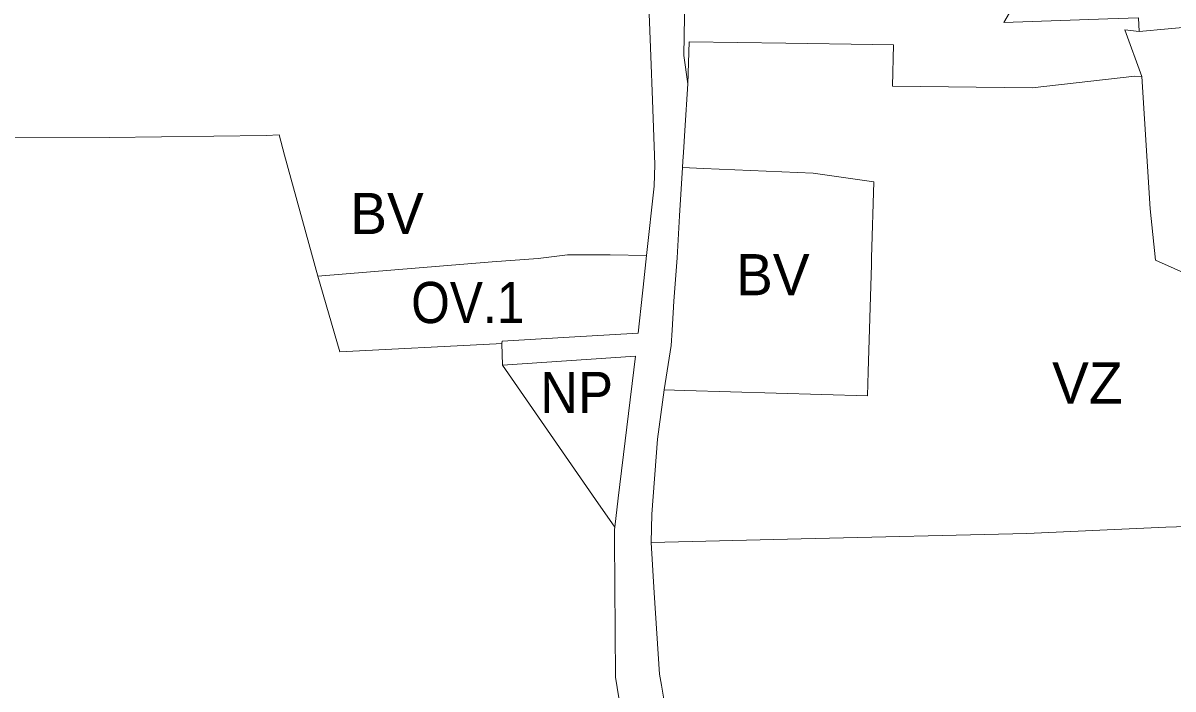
# Model space of a CAD drawing. Extents: x -650451 to -642268, y -1075216 to -1066610.
# Drawn here: x -643994.3 to -643659.8, y -1070322.5 to -1070128.6 of the extents above; entities that cross this region are included whole.
import ezdxf

# ---------------------------------------------------------------- set-up
doc = ezdxf.new("R2010")
doc.units = 0
doc.header["$LTSCALE"] = 4.8
for name, color, linetype, lineweight in [('11', 7, 'Continuous', 13), ('15', 7, 'Continuous', 13), ('19', 7, 'Continuous', 13), ('3', 7, 'Continuous', 13), ('36', 7, 'Continuous', 13), ('46', 7, 'Continuous', 13), ('48', 7, 'Continuous', 13)]:
    doc.layers.add(name, color=color, linetype=linetype, lineweight=lineweight)
doc.layers.add('62', color=7, linetype='Continuous')

msp = doc.modelspace()

# ---------------------------------------------------------------- linework, layer by layer
at = {"layer": '11'}
for points in [[(-643908.56, -1070202.27), (-643857.8, -1070198.08), (-643844.39, -1070197.15), (-643835.87, -1070196.07), (-643823.46, -1070196.05), (-643812.86, -1070196.23)], [(-643812.86, -1070196.23), (-643813.9, -1070205.47), (-643814.1, -1070207.22), (-643815.36, -1070218.9), (-643837.09, -1070220.17), (-643854.85, -1070221.2), (-643854.98, -1070221.87)], [(-643854.98, -1070221.87), (-643856.64, -1070221.95), (-643902.14, -1070224.35), (-643908.56, -1070202.27)]]:
    msp.add_lwpolyline(points, dxfattribs=at)
at = {"layer": '15'}
for points in [[(-643732.39, -1070061.88), (-643738.08, -1070064.14), (-643748.14, -1070063.86), (-643752.98, -1070063.79), (-643753.18, -1070063.79), (-643759.23, -1070063.69), (-643759.22, -1070063.39), (-643765.22, -1070063.29), (-643765.22, -1070063.59), (-643771, -1070063.49), (-643785.75, -1070067.9), (-643787.98, -1070068.57), (-643801.31, -1070092.6), (-643802.09, -1070138.03), (-643800.88, -1070146.32)], [(-643669.62, -1070131.03), (-643669.82, -1070127.03), (-643678.68, -1070127.35), (-643708.96, -1070128.43), (-643691.59, -1070098.73)], [(-643812.86, -1070196.23), (-643810.68, -1070176.11), (-643810.49, -1070169.78), (-643811.2, -1070151.02), (-643811.64, -1070138.19), (-643812.42, -1070118.32), (-643812.68, -1070111.83), (-643814.47, -1070109.04), (-643821.16, -1070104.38)], [(-643377.4, -1070373.91), (-643369.96, -1070370.47), (-643364.57, -1070372.2), (-643339.86, -1070385.67), (-643332.76, -1070386.69), (-643328.7, -1070384.53), (-643327.21, -1070380.37), (-643328.23, -1070357.18), (-643328.02, -1070343.62), (-643327.74, -1070325.85), (-643328, -1070321.45), (-643328.87, -1070307.62), (-643333.3, -1070289.47), (-643344.72, -1070271.05), (-643381.54, -1070218.57), (-643429.35, -1070151.61), (-643452.86, -1070119.74), (-643459.33, -1070122.38), (-643478.13, -1070124.25), (-643485.57, -1070124.21), (-643547.12, -1070123.91), (-643652.76, -1070129.53), (-643669.62, -1070131.03)], [(-643800.88, -1070146.32), (-643801.76, -1070159.87), (-643802.15, -1070166.28), (-643802.31, -1070168.83), (-643802.43, -1070170.63)], [(-643802.43, -1070170.63), (-643803.34, -1070184.74), (-643804.01, -1070196.99), (-643804.92, -1070209.57), (-643805.46, -1070217.99), (-643805.74, -1070222.47), (-643807.76, -1070235.39)], [(-643854.98, -1070221.87), (-643854.85, -1070221.2), (-643837.09, -1070220.17), (-643815.36, -1070218.9), (-643814.1, -1070207.22), (-643813.9, -1070205.47), (-643812.86, -1070196.23)], [(-643822.14, -1070275.37), (-643821.11, -1070266.91), (-643816.06, -1070225.6), (-643854.84, -1070228.19), (-643854.98, -1070221.87)], [(-643807.76, -1070235.39), (-643809.72, -1070249.74), (-643811.34, -1070271.58), (-643811.51, -1070279.84)], [(-643814.11, -1070367.77), (-643821.9, -1070319.09), (-643822.26, -1070278.85), (-643822.17, -1070276.1), (-643822.14, -1070275.37)], [(-643811.51, -1070279.84), (-643810.66, -1070294.47), (-643809.12, -1070318.15), (-643808.57, -1070321.41), (-643801.16, -1070365.63), (-643793.87, -1070409.87), (-643790.37, -1070435.73), (-643789.85, -1070457.79), (-643792.3, -1070491.62), (-643685.51, -1070484.11), (-643556.78, -1070472.69), (-643535.28, -1070462.36), (-643515.79, -1070458.2), (-643493.94, -1070454.16), (-643457.91, -1070443.79), (-643443.3, -1070435.98)]]:
    msp.add_lwpolyline(points, dxfattribs=at)
at = {"layer": '19'}
for points in [[(-643800.88, -1070146.32), (-643802.09, -1070138.03), (-643801.31, -1070092.6), (-643787.98, -1070068.57), (-643785.75, -1070067.9), (-643771, -1070063.49), (-643765.22, -1070063.59), (-643765.22, -1070063.29), (-643759.22, -1070063.39), (-643759.23, -1070063.69), (-643753.18, -1070063.79), (-643752.98, -1070063.79), (-643748.14, -1070063.86), (-643738.08, -1070064.14), (-643732.39, -1070061.88)], [(-643691.59, -1070098.73), (-643708.96, -1070128.43), (-643678.68, -1070127.35), (-643669.82, -1070127.03), (-643669.62, -1070131.03)], [(-643669.62, -1070131.03), (-643673.76, -1070130.59), (-643668.79, -1070144.14)], [(-643668.79, -1070144.14), (-643670.82, -1070144.04), (-643700.68, -1070147.41), (-643741.39, -1070146.98), (-643741.1, -1070134.91), (-643747.09, -1070134.82), (-643772.38, -1070134.47), (-643800.5, -1070134.09), (-643800.88, -1070146.32)]]:
    msp.add_lwpolyline(points, dxfattribs=at)
at = {"layer": '3'}
for points in [[(-643812.68, -1070111.83), (-643812.42, -1070118.32), (-643811.64, -1070138.19), (-643811.2, -1070151.02), (-643810.49, -1070169.78), (-643810.68, -1070176.11), (-643812.86, -1070196.23)], [(-643908.56, -1070202.27), (-643918.18, -1070167.04), (-643919.79, -1070161.15), (-643923.5, -1070161.3), (-643969.23, -1070161.95), (-644001.25, -1070162.03), (-644029.46, -1070162.44), (-644047.4, -1070162.68), (-644050.01, -1070138.19)], [(-643807.76, -1070235.39), (-643805.74, -1070222.47), (-643805.46, -1070217.99), (-643804.92, -1070209.57), (-643804.01, -1070196.99), (-643803.34, -1070184.74), (-643802.43, -1070170.63)], [(-643802.43, -1070170.63), (-643796.35, -1070170.9), (-643764.44, -1070172.34), (-643746.8, -1070174.87), (-643747.45, -1070196.95), (-643747.5, -1070198.86), (-643748.41, -1070230.13), (-643748.61, -1070237.12), (-643801.78, -1070235.57), (-643807.76, -1070235.39)], [(-643812.86, -1070196.23), (-643823.46, -1070196.05), (-643835.87, -1070196.07), (-643844.39, -1070197.15), (-643857.8, -1070198.08), (-643908.56, -1070202.27)]]:
    msp.add_lwpolyline(points, dxfattribs=at)
at = {"layer": '36'}
for points in [[(-643800.88, -1070146.32), (-643800.5, -1070134.09), (-643772.38, -1070134.47), (-643747.09, -1070134.82), (-643741.1, -1070134.91), (-643741.39, -1070146.98), (-643700.68, -1070147.41), (-643670.82, -1070144.04), (-643668.79, -1070144.14)], [(-643668.79, -1070144.14), (-643666.41, -1070182.7), (-643664.83, -1070197.66), (-643642.28, -1070207.75), (-643641.8, -1070209.42), (-643639.36, -1070217.78), (-643639.49, -1070235.43), (-643639.63, -1070253.09), (-643639.79, -1070274.68), (-643661.89, -1070275.34), (-643702.24, -1070277.22), (-643767.92, -1070278.79), (-643811.51, -1070279.84)], [(-643802.43, -1070170.63), (-643802.31, -1070168.83), (-643802.15, -1070166.28), (-643801.76, -1070159.87), (-643800.88, -1070146.32)], [(-643807.76, -1070235.39), (-643801.78, -1070235.57), (-643748.61, -1070237.12), (-643748.41, -1070230.13), (-643747.5, -1070198.86), (-643747.45, -1070196.95), (-643746.8, -1070174.87), (-643764.44, -1070172.34), (-643796.35, -1070170.9), (-643802.43, -1070170.63)], [(-643811.51, -1070279.84), (-643811.34, -1070271.58), (-643809.72, -1070249.74), (-643807.76, -1070235.39)]]:
    msp.add_lwpolyline(points, dxfattribs=at)
at = {"layer": '46'}
for points in [[(-643669.62, -1070131.03), (-643652.76, -1070129.53), (-643547.12, -1070123.91), (-643485.57, -1070124.21), (-643478.13, -1070124.25), (-643459.33, -1070122.38), (-643452.86, -1070119.74), (-643429.35, -1070151.61), (-643381.54, -1070218.57), (-643344.72, -1070271.05), (-643333.3, -1070289.47), (-643328.87, -1070307.62), (-643328, -1070321.45), (-643327.74, -1070325.85), (-643328.02, -1070343.62), (-643328.23, -1070357.18), (-643327.21, -1070380.37), (-643328.7, -1070384.53), (-643332.76, -1070386.69), (-643339.86, -1070385.67), (-643364.57, -1070372.2), (-643369.96, -1070370.47), (-643377.4, -1070373.91)], [(-643668.79, -1070144.14), (-643673.76, -1070130.59), (-643669.62, -1070131.03)], [(-644050.01, -1070138.19), (-644047.4, -1070162.68), (-644029.46, -1070162.44), (-644001.25, -1070162.03), (-643969.23, -1070161.95), (-643923.5, -1070161.3), (-643919.79, -1070161.15), (-643918.18, -1070167.04), (-643908.56, -1070202.27)], [(-643811.51, -1070279.84), (-643767.92, -1070278.79), (-643702.24, -1070277.22), (-643661.89, -1070275.34), (-643639.79, -1070274.68), (-643639.63, -1070253.09), (-643639.49, -1070235.43), (-643639.36, -1070217.78), (-643641.8, -1070209.42), (-643642.28, -1070207.75), (-643664.83, -1070197.66), (-643666.41, -1070182.7), (-643668.79, -1070144.14)], [(-643908.56, -1070202.27), (-643902.14, -1070224.35), (-643856.64, -1070221.95), (-643854.98, -1070221.87), (-643854.84, -1070228.19)], [(-643854.84, -1070228.19), (-643827.73, -1070267.3), (-643822.14, -1070275.37)], [(-643822.14, -1070275.37), (-643822.17, -1070276.1), (-643822.26, -1070278.85), (-643821.9, -1070319.09), (-643814.11, -1070367.77)], [(-643443.3, -1070435.98), (-643457.91, -1070443.79), (-643493.94, -1070454.16), (-643515.79, -1070458.2), (-643535.28, -1070462.36), (-643556.78, -1070472.69), (-643685.51, -1070484.11), (-643792.3, -1070491.62), (-643789.85, -1070457.79), (-643790.37, -1070435.73), (-643793.87, -1070409.87), (-643801.16, -1070365.63), (-643808.57, -1070321.41), (-643809.12, -1070318.15), (-643810.66, -1070294.47), (-643811.51, -1070279.84)]]:
    msp.add_lwpolyline(points, dxfattribs=at)
at = {"layer": '48'}
for points in [[(-643854.84, -1070228.19), (-643816.06, -1070225.6), (-643821.11, -1070266.91), (-643822.14, -1070275.37)], [(-643822.14, -1070275.37), (-643827.73, -1070267.3), (-643854.84, -1070228.19)]]:
    msp.add_lwpolyline(points, dxfattribs=at)

# ---------------------------------------------------------------- texts
at = {"layer": '62'}
for s, p in [('BV', (-643899.099, -1070190.041)), ('BV', (-643786.863, -1070207.859)), ('VZ', (-643694.926, -1070239.39))]:
    msp.add_text(s, height=12, dxfattribs=at).set_placement(p)
for s, width, p in [('OV.1', 0.9, (-643881.349, -1070215.959)), ('NP', 0.95, (-643843.815, -1070242.16))]:
    msp.add_text(s, height=12, dxfattribs=dict(at, width=width)).set_placement(p)

doc.saveas('drawing.dxf')
